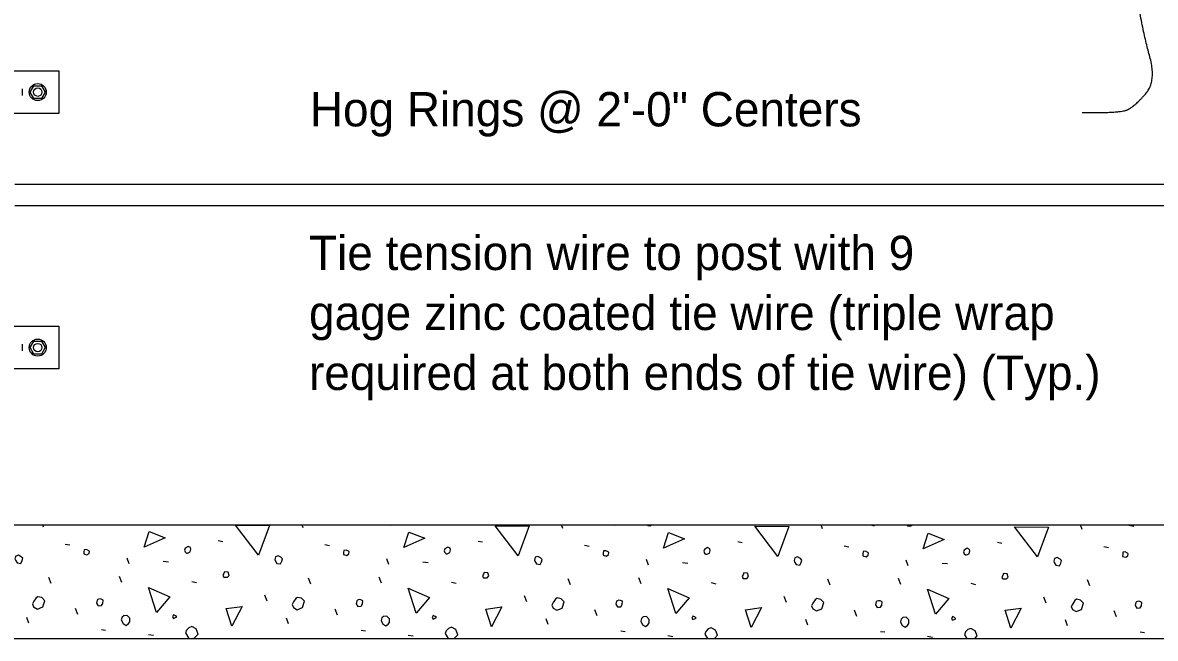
# Model space of a CAD drawing. Extents: x 0 to 41.2, y 0 to 26.
# Drawn here: x 12.4 to 19.05, y 13.47 to 17.08 of the extents above; entities that cross this region are included whole.
import ezdxf

# ---------------------------------------------------------------- set-up
doc = ezdxf.new("R2010")
doc.units = 0
for name, color, linetype in [('Dimension', 7, 'Continuous'), ('Miscellaneous', 7, 'Continuous'), ('SteelMisc', 7, 'Continuous'), ('SupstrConc', 7, 'Continuous'), ('TextStructures', 7, 'Continuous')]:
    doc.layers.add(name, color=color, linetype=linetype)

msp = doc.modelspace()

# ---------------------------------------------------------------- linework, layer by layer
at = {"layer": 'Dimension'}
msp.add_open_spline([(18.6159, 16.5559), (18.8387, 16.5523), (18.9236, 16.5913), (19.0545, 16.74), (18.9696, 17.0374), (18.9272, 17.3027)], degree=2, dxfattribs=at)
at = {"layer": 'Miscellaneous'}
for p, q in [((12.5219, 14.122), (12.5167, 14.1361)), ((14.0457, 14.1184), (14.0392, 14.1361)), ((15.5695, 14.1149), (15.5617, 14.1361)), ((15.8647, 14.1361), (15.8718, 14.1344)), ((17.0933, 14.1114), (17.0842, 14.1361)), ((17.3744, 14.1361), (17.3956, 14.1308)), ((18.6171, 14.1078), (18.6067, 14.1361)), ((18.8911, 14.1344), (18.9194, 14.1273)), ((13.5472, 14.0442), (13.5737, 14.0389)), ((15.071, 14.0407), (15.0975, 14.0354)), ((16.5948, 14.0371), (16.6213, 14.0318)), ((18.1186, 14.0336), (18.1451, 14.0283)), ((12.6492, 14.023), (12.6757, 14.0177)), ((14.173, 14.0194), (14.1995, 14.0141)), ((15.6968, 14.0159), (15.7233, 14.0106)), ((17.2206, 14.0124), (17.2471, 14.0071)), ((18.7444, 14.0088), (18.7709, 14.0035)), ((13.0239, 13.9063), (13.0115, 13.9399)), ((13.2237, 13.9222), (13.2555, 13.9187)), ((14.5477, 13.9028), (14.5354, 13.9364)), ((14.7475, 13.9187), (14.7793, 13.9151)), ((16.0716, 13.8992), (16.0592, 13.9328)), ((16.2713, 13.9151), (16.3031, 13.9116)), ((17.5954, 13.8957), (17.583, 13.9293)), ((17.7951, 13.9116), (17.8269, 13.9081)), ((12.5661, 13.7914), (12.5519, 13.8268)), ((12.9815, 13.7967), (12.9674, 13.8321)), ((14.5053, 13.7932), (14.4912, 13.8285)), ((13.3916, 13.8038), (13.4199, 13.7967)), ((14.0899, 13.7879), (14.0757, 13.8232)), ((14.9154, 13.8002), (14.9437, 13.7932)), ((15.6137, 13.7843), (15.5996, 13.8197)), ((16.0291, 13.7896), (16.015, 13.825)), ((16.4392, 13.7967), (16.4675, 13.7896)), ((17.1375, 13.7808), (17.1234, 13.8162)), ((17.5529, 13.7861), (17.5388, 13.8215)), ((17.9631, 13.7932), (17.9913, 13.7861)), ((18.6613, 13.7773), (18.6472, 13.8126)), ((13.8336, 13.6871), (13.8194, 13.7225)), ((15.3574, 13.6836), (15.3432, 13.7189)), ((16.8812, 13.68), (16.867, 13.7154)), ((18.405, 13.6765), (18.3909, 13.7119)), ((12.7234, 13.6093), (12.7093, 13.6447)), ((14.2472, 13.6058), (14.2331, 13.6411)), ((15.771, 13.6023), (15.7569, 13.6376)), ((17.2948, 13.5987), (17.2807, 13.6341)), ((18.8187, 13.5952), (18.8045, 13.6305)), ((12.4353, 13.5581), (12.4229, 13.5916)), ((13.9591, 13.5545), (13.9467, 13.5881)), ((15.4829, 13.551), (15.4705, 13.5846)), ((17.0067, 13.5475), (16.9943, 13.581)), ((18.5305, 13.5439), (18.5181, 13.5775)), ((12.8613, 13.5209), (12.886, 13.5174)), ((14.3851, 13.5174), (14.4099, 13.5139)), ((15.9089, 13.5139), (15.9337, 13.5103)), ((17.4327, 13.5103), (17.4575, 13.5068)), ((18.9565, 13.5068), (18.9813, 13.5033)), ((13.1371, 13.4927), (13.1671, 13.4873)), ((14.6609, 13.4891), (14.6909, 13.4838)), ((16.1847, 13.4856), (16.2147, 13.4803)), ((17.7085, 13.482), (17.7386, 13.4767))]:
    msp.add_line(p, q, dxfattribs=at)
for points in [[(13.1123, 14.0053), (13.1406, 14.0972), (13.2343, 14.0601), (13.1123, 14.0053)], [(13.7823, 13.9576), (13.6479, 14.1344), (13.8477, 14.1326), (13.7823, 13.9576)], [(14.5442, 14.1361), (14.5566, 14.1344), (14.5607, 14.1361)], [(14.6361, 14.0018), (14.6644, 14.0937), (14.7581, 14.0566), (14.6361, 14.0018)], [(15.3061, 13.954), (15.1718, 14.1308), (15.3715, 14.129), (15.3061, 13.954)], [(16.0645, 14.1361), (16.068, 14.1326)], [(16.068, 14.1326), (16.0804, 14.1308), (16.0928, 14.1361)], [(16.8299, 13.9505), (16.6956, 14.1273), (16.8953, 14.1255), (16.8299, 13.9505)], [(17.5848, 14.1361), (17.5918, 14.129)], [(17.5918, 14.129), (17.6042, 14.1273), (17.6166, 14.1326), (17.6178, 14.1361)], [(18.3537, 13.947), (18.2194, 14.1237), (18.4191, 14.122), (18.3537, 13.947)], [(16.1599, 13.9982), (16.1882, 14.0902), (16.2819, 14.053), (16.1599, 13.9982)], [(17.6838, 13.9947), (17.712, 14.0866), (17.8057, 14.0495), (17.6838, 13.9947)], [(12.757, 13.9646), (12.7764, 13.9593), (12.7888, 13.9682), (12.7906, 13.9806), (12.787, 13.9841), (12.7729, 13.9912), (12.7605, 13.9894), (12.7588, 13.977), (12.757, 13.9646)], [(13.3598, 13.9699), (13.3669, 13.9699), (13.381, 13.977), (13.3863, 13.9929), (13.3845, 14.0018), (13.3704, 14.0088), (13.3527, 13.9982), (13.3492, 13.9876), (13.3527, 13.977), (13.3598, 13.9699)], [(14.2808, 13.9611), (14.3003, 13.9558), (14.3126, 13.9646), (14.3144, 13.977), (14.3109, 13.9806), (14.2967, 13.9876), (14.2843, 13.9859), (14.2826, 13.9735), (14.2808, 13.9611)], [(14.8836, 13.9664), (14.8907, 13.9664), (14.9048, 13.9735), (14.9101, 13.9894), (14.9084, 13.9982), (14.8942, 14.0053), (14.8765, 13.9947), (14.873, 13.9841), (14.8765, 13.9735), (14.8836, 13.9664)], [(15.8046, 13.9576), (15.8241, 13.9523), (15.8364, 13.9611), (15.8382, 13.9735), (15.8347, 13.977), (15.8205, 13.9841), (15.8082, 13.9823), (15.8064, 13.9699), (15.8046, 13.9576)], [(16.4074, 13.9629), (16.4145, 13.9629), (16.4286, 13.9699), (16.4339, 13.9859), (16.4322, 13.9947), (16.418, 14.0018), (16.4004, 13.9912), (16.3968, 13.9806), (16.4004, 13.9699), (16.4074, 13.9629)], [(17.3284, 13.954), (17.3479, 13.9487), (17.3603, 13.9576), (17.362, 13.9699), (17.3585, 13.9735), (17.3443, 13.9806), (17.332, 13.9788), (17.3302, 13.9664), (17.3284, 13.954)], [(17.9312, 13.9593), (17.9383, 13.9593), (17.9525, 13.9664), (17.9578, 13.9823), (17.956, 13.9912), (17.9419, 13.9982), (17.9242, 13.9876), (17.9206, 13.977), (17.9242, 13.9664), (17.9312, 13.9593)], [(18.8523, 13.9505), (18.8717, 13.9452), (18.8841, 13.954), (18.8858, 13.9664), (18.8823, 13.9699), (18.8682, 13.977), (18.8558, 13.9753), (18.854, 13.9629), (18.8523, 13.9505)], [(12.3575, 13.9293), (12.3663, 13.9134), (12.3875, 13.9098), (12.3964, 13.9258), (12.3999, 13.9399), (12.3911, 13.9487), (12.3752, 13.9576), (12.3592, 13.9523), (12.3539, 13.9364), (12.3575, 13.9293)], [(13.8813, 13.9258), (13.8901, 13.9098), (13.9113, 13.9063), (13.9202, 13.9222), (13.9237, 13.9364), (13.9149, 13.9452), (13.899, 13.954), (13.8831, 13.9487), (13.8778, 13.9328), (13.8813, 13.9258)], [(15.4051, 13.9222), (15.4139, 13.9063), (15.4352, 13.9028), (15.444, 13.9187), (15.4475, 13.9328), (15.4387, 13.9417), (15.4228, 13.9505), (15.4069, 13.9452), (15.4016, 13.9293), (15.4051, 13.9222)], [(16.9289, 13.9187), (16.9378, 13.9028), (16.959, 13.8992), (16.9678, 13.9151), (16.9713, 13.9293), (16.9625, 13.9381), (16.9466, 13.947), (16.9307, 13.9417), (16.9254, 13.9258), (16.9289, 13.9187)], [(18.4527, 13.9151), (18.4616, 13.8992), (18.4828, 13.8957), (18.4916, 13.9116), (18.4952, 13.9258), (18.4863, 13.9346), (18.4704, 13.9434), (18.4545, 13.9381), (18.4492, 13.9222), (18.4527, 13.9151)], [(13.579, 13.8285), (13.6002, 13.8285), (13.6108, 13.8391), (13.6055, 13.8586), (13.5825, 13.8603), (13.579, 13.8497), (13.5737, 13.8409), (13.579, 13.8285), (13.5755, 13.8321)], [(15.1028, 13.825), (15.124, 13.825), (15.1346, 13.8356), (15.1293, 13.855), (15.1064, 13.8568), (15.1028, 13.8462), (15.0975, 13.8374), (15.1028, 13.825), (15.0993, 13.8285)], [(16.6266, 13.8215), (16.6478, 13.8215), (16.6585, 13.8321), (16.6531, 13.8515), (16.6302, 13.8533), (16.6266, 13.8427), (16.6213, 13.8338), (16.6266, 13.8215), (16.6231, 13.825)], [(18.1504, 13.8179), (18.1717, 13.8179), (18.1823, 13.8285), (18.177, 13.848), (18.154, 13.8497), (18.1504, 13.8391), (18.1451, 13.8303), (18.1504, 13.8179), (18.1469, 13.8215)], [(13.1848, 13.6217), (13.1371, 13.7684), (13.2626, 13.7136), (13.1848, 13.6217)], [(14.7086, 13.6182), (14.6609, 13.7649), (14.7864, 13.7101), (14.7086, 13.6182)], [(16.2324, 13.6146), (16.1847, 13.7614), (16.3102, 13.7066), (16.2324, 13.6146)], [(12.4635, 13.6535), (12.4865, 13.6411), (12.5166, 13.6535), (12.5289, 13.6906), (12.5113, 13.7083), (12.4883, 13.7136), (12.4777, 13.7066), (12.4653, 13.6871), (12.4565, 13.6712), (12.4635, 13.6535)], [(12.833, 13.6765), (12.8418, 13.6606), (12.8613, 13.6624), (12.8701, 13.6747), (12.8719, 13.6942), (12.8595, 13.6995), (12.8507, 13.7012), (12.8401, 13.6977), (12.8365, 13.6942), (12.833, 13.6765)], [(13.9874, 13.65), (14.0103, 13.6376), (14.0404, 13.65), (14.0528, 13.6871), (14.0351, 13.7048), (14.0121, 13.7101), (14.0015, 13.703), (13.9891, 13.6836), (13.9803, 13.6677), (13.9874, 13.65)], [(14.3568, 13.673), (14.3657, 13.6571), (14.3851, 13.6588), (14.3939, 13.6712), (14.3957, 13.6906), (14.3833, 13.6959), (14.3745, 13.6977), (14.3639, 13.6942), (14.3604, 13.6906), (14.3568, 13.673)], [(15.5112, 13.6464), (15.5342, 13.6341), (15.5642, 13.6464), (15.5766, 13.6836), (15.5589, 13.7012), (15.5359, 13.7066), (15.5253, 13.6995), (15.5129, 13.68), (15.5041, 13.6641), (15.5112, 13.6464)], [(15.8806, 13.6694), (15.8895, 13.6535), (15.9089, 13.6553), (15.9178, 13.6677), (15.9195, 13.6871), (15.9072, 13.6924), (15.8983, 13.6942), (15.8877, 13.6906), (15.8842, 13.6871), (15.8806, 13.6694)], [(17.035, 13.6429), (17.058, 13.6305), (17.088, 13.6429), (17.1004, 13.68), (17.0827, 13.6977), (17.0597, 13.703), (17.0491, 13.6959), (17.0368, 13.6765), (17.0279, 13.6606), (17.035, 13.6429)], [(17.7562, 13.6111), (17.7085, 13.7578), (17.834, 13.703), (17.7562, 13.6111)], [(18.5588, 13.6394), (18.5818, 13.627), (18.6118, 13.6394), (18.6242, 13.6765), (18.6065, 13.6942), (18.5836, 13.6995), (18.5729, 13.6924), (18.5606, 13.673), (18.5517, 13.6571), (18.5588, 13.6394)], [(13.6267, 13.5404), (13.5931, 13.6447), (13.6868, 13.6571), (13.6267, 13.5404)], [(15.1505, 13.5368), (15.117, 13.6411), (15.2107, 13.6535), (15.1505, 13.5368)], [(16.6744, 13.5333), (16.6408, 13.6376), (16.7345, 13.65), (16.6744, 13.5333)], [(17.4044, 13.6659), (17.4133, 13.65), (17.4327, 13.6518), (17.4416, 13.6641), (17.4433, 13.6836), (17.431, 13.6889), (17.4221, 13.6906), (17.4115, 13.6871), (17.408, 13.6836), (17.4044, 13.6659)], [(18.1982, 13.5298), (18.1646, 13.6341), (18.2583, 13.6464), (18.1982, 13.5298)], [(18.9283, 13.6624), (18.9371, 13.6464), (18.9565, 13.6482), (18.9654, 13.6606), (18.9672, 13.68), (18.9548, 13.6853), (18.9459, 13.6871), (18.9353, 13.6836), (18.9318, 13.68), (18.9283, 13.6624)], [(12.978, 13.5775), (12.9886, 13.5563), (13.0062, 13.5457), (13.0204, 13.5563), (13.0275, 13.5669), (13.0275, 13.5881), (13.0115, 13.604), (12.9921, 13.6023), (12.9833, 13.5934), (12.978, 13.5775)], [(13.2838, 13.5863), (13.3032, 13.5952), (13.2962, 13.6023), (13.2838, 13.6076), (13.2785, 13.5952), (13.2838, 13.5863)], [(14.5018, 13.574), (14.5124, 13.5528), (14.5301, 13.5421), (14.5442, 13.5528), (14.5513, 13.5634), (14.5513, 13.5846), (14.5354, 13.6005), (14.5159, 13.5987), (14.5071, 13.5899), (14.5018, 13.574)], [(14.8076, 13.5828), (14.827, 13.5916), (14.82, 13.5987), (14.8076, 13.604), (14.8023, 13.5916), (14.8076, 13.5828)], [(16.0256, 13.5704), (16.0362, 13.5492), (16.0539, 13.5386), (16.068, 13.5492), (16.0751, 13.5598), (16.0751, 13.581), (16.0592, 13.5969), (16.0397, 13.5952), (16.0309, 13.5863), (16.0256, 13.5704)], [(16.3314, 13.5793), (16.3509, 13.5881), (16.3438, 13.5952), (16.3314, 13.6005), (16.3261, 13.5881), (16.3314, 13.5793)], [(17.5494, 13.5669), (17.56, 13.5457), (17.5777, 13.5351), (17.5918, 13.5457), (17.5989, 13.5563), (17.5989, 13.5775), (17.583, 13.5934), (17.5635, 13.5916), (17.5547, 13.5828), (17.5494, 13.5669)], [(17.8552, 13.5757), (17.8747, 13.5846), (17.8676, 13.5916), (17.8552, 13.5969), (17.8499, 13.5846), (17.8552, 13.5757)], [(13.4038, 13.4695), (13.4093, 13.475), (13.4287, 13.4944), (13.4164, 13.5245), (13.3916, 13.5386), (13.3739, 13.5315), (13.3598, 13.5174), (13.3545, 13.5015)], [(13.3545, 13.5015), (13.3743, 13.4695)], [(14.9311, 13.4695), (14.9331, 13.4714), (14.9526, 13.4909), (14.9402, 13.5209), (14.9154, 13.5351), (14.8978, 13.528), (14.8836, 13.5139), (14.8783, 13.498)], [(14.8783, 13.498), (14.896, 13.4695)], [(16.4585, 13.4695), (16.4764, 13.4873), (16.464, 13.5174), (16.4392, 13.5315), (16.4216, 13.5245), (16.4074, 13.5103), (16.4021, 13.4944)], [(16.4021, 13.4944), (16.4176, 13.4695)], [(17.9858, 13.4695), (18.0002, 13.4838), (17.9878, 13.5139), (17.9631, 13.528), (17.9454, 13.5209), (17.9312, 13.5068), (17.9259, 13.4909)], [(17.9259, 13.4909), (17.9392, 13.4695)]]:
    msp.add_lwpolyline(points, dxfattribs=at)
at = {"layer": 'SteelMisc'}
for p, q in [((11.8002, 16.801), (12.6122, 16.801)), ((12.6122, 16.801), (12.6122, 16.551)), ((12.399, 16.6566), (12.399, 16.6955)), ((12.6122, 16.551), (11.8002, 16.551)), ((11.8002, 15.301), (12.6122, 15.301)), ((12.6122, 15.301), (12.6122, 15.051)), ((12.399, 15.1566), (12.399, 15.1955)), ((12.6122, 15.051), (11.8002, 15.051))]:
    msp.add_line(p, q, dxfattribs=at)
for points in [[(12.4655, 16.7135), (12.5089, 16.7135), (12.5305, 16.676), (12.5089, 16.6385), (12.4655, 16.6385), (12.4439, 16.676)], [(12.4655, 15.2135), (12.5089, 15.2135), (12.5305, 15.176), (12.5089, 15.1385), (12.4655, 15.1385), (12.4439, 15.176)]]:
    msp.add_lwpolyline(points, close=True, dxfattribs=at)
for centre, radius in [((12.4872, 16.676), 0.05), ((12.4872, 16.676), 0.025), ((12.4872, 15.176), 0.05), ((12.4872, 15.176), 0.025)]:
    msp.add_circle(centre, radius, dxfattribs=at)
at = {"layer": 'SupstrConc'}
for p, q in [((12.3521, 16.1361), (22.0604, 16.1361)), ((12.3521, 16.0111), (22.0604, 16.0111)), ((0.8193, 14.1361), (23.5931, 14.1361)), ((0.8193, 13.4695), (23.5931, 13.4695))]:
    msp.add_line(p, q, dxfattribs=at)

# ---------------------------------------------------------------- texts
at = {"layer": 'Dimension'}
for s, p in [('Tie tension wire to post with 9 ', (14.0794, 15.6312)), ('gage zinc coated tie wire (triple wrap ', (14.0794, 15.2792)), ('required at both ends of tie wire) (Typ.)', (14.0794, 14.9272))]:
    msp.add_text(s, height=0.2016, dxfattribs=at).set_placement(p)
at = {"layer": 'TextStructures'}
msp.add_text('Hog Rings @ 2\'-0" Centers', height=0.2016, dxfattribs=at).set_placement((14.0841, 16.4746))

doc.saveas('drawing.dxf')
